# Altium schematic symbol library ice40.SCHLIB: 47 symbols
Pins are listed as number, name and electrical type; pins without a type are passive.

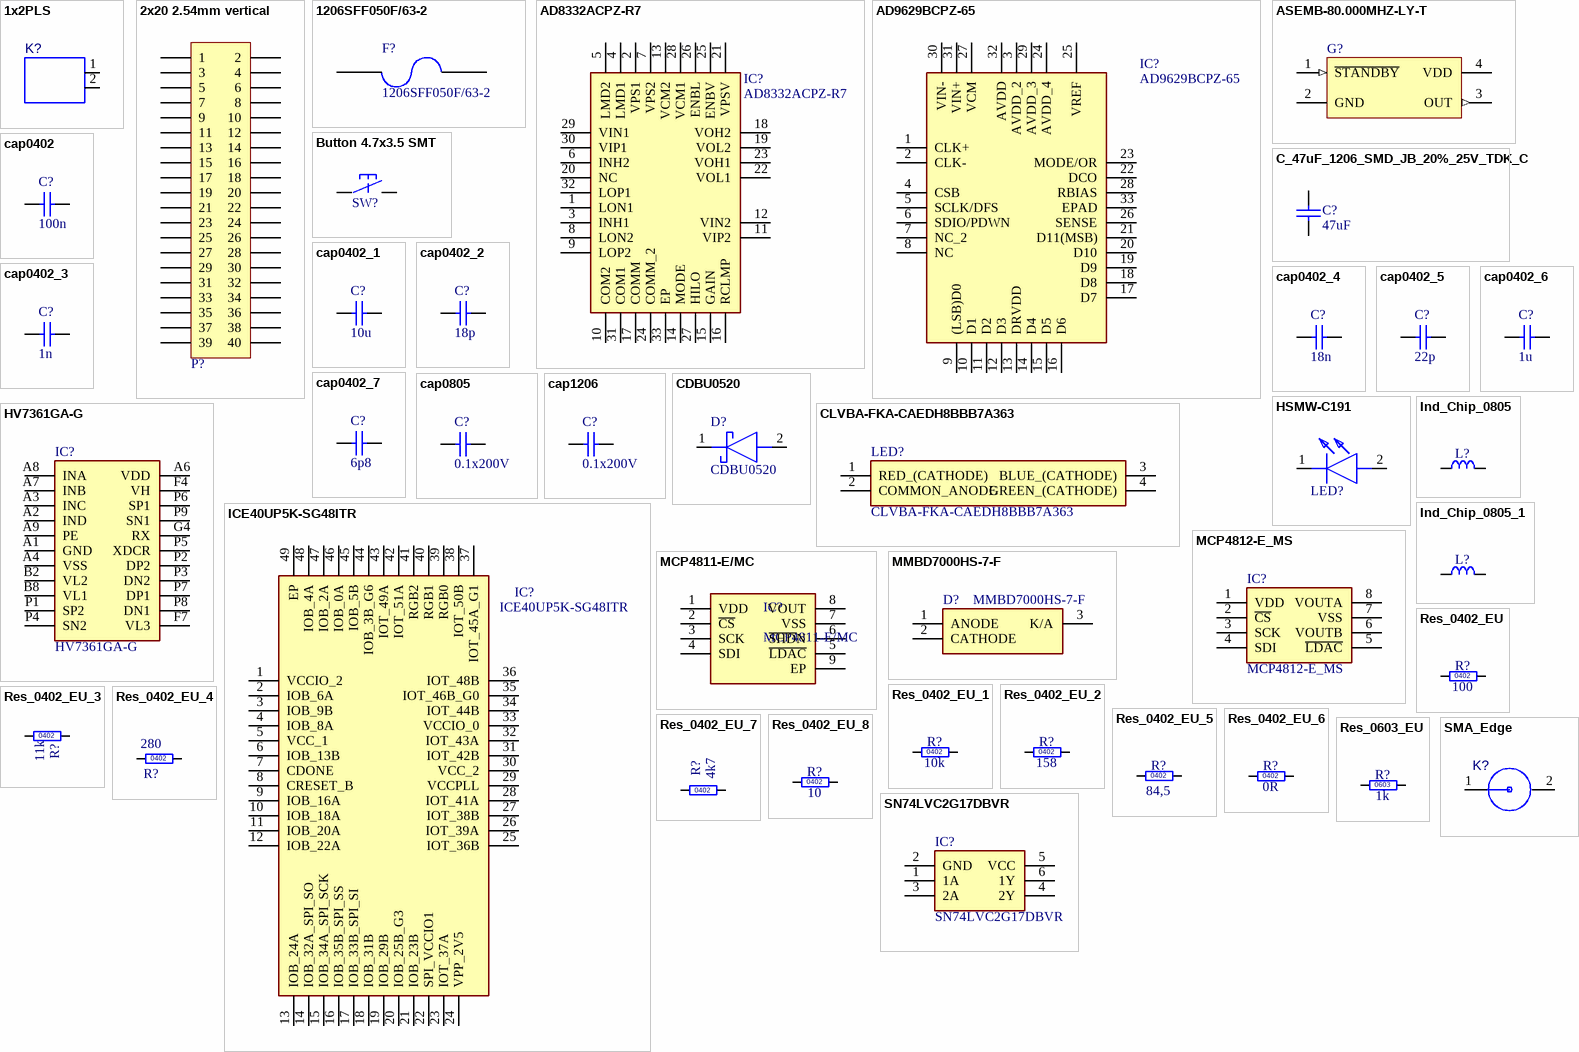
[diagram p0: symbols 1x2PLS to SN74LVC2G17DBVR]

## 1x2PLS
designator K?  (value not drawn)
footprint JUMPER2
pins: 1, 2

## 2x20 2.54mm vertical
designator P?  (value not drawn)
Header, 40-Pin
footprint PLD-40
pins: 1, 2, 3, 4, 5, 6, 7, 8, 9, 10, 11, 12, 13, 14, 15, 16, 17, 18, 19, 20, 21, 22, 23, 24, 25, 26, 27, 28, 29, 30, 31, 32, 33, 34, 35, 36, 37, 38, 39, 40

## 1206SFF050F/63-2
designator F?
500mA AC 63V DC Fuse Board Mount Surface Mount 1206; ATT Technology: SMD; ATT Fuse size: 1206
footprint FUSE_1206 (FUSE, 2-Leads, Body 3.2x1.60mm, IPC Medium Density)
pins: 1, 2

## AD8332ACPZ-R7
designator IC?
Integrated Circuit; Manufacturer_Name: Analog Devices
footprint QFN50P500X500X100-33N
pins: 1 LON1, 2 VPS1, 3 INH1, 4 LMD1, 5 LMD2, 6 INH2, 7 VPS2, 8 LON2, 9 LOP2, 10 COM2, 11 VIP2, 12 VIN2, 13 VCM2, 14 MODE, 15 GAIN, 16 RCLMP, 17 COMM, 18 VOH2, 19 VOL2, 20 NC, 21 VPSV, 22 VOL1, 23 VOH1, 24 COMM_2, 25 ENBV, 26 ENBL, 27 HILO, 28 VCM1, 29 VIN1, 30 VIP1, 31 COM1, 32 LOP1, 33 EP

## AD9629BCPZ-65
designator IC?
Integrated Circuit; Manufacturer_Name: Analog Devices
footprint QFN50P500X500X100-33N
pins: 1 CLK+, 2 CLK-, 3 AVDD_2, 4 CSB, 5 SCLK/DFS, 6 SDIO/PDWN, 7 NC_2, 8 NC, 9 (LSB)D0, 10 D1, 11 D2, 12 D3, 13 DRVDD, 14 D4, 15 D5, 16 D6, 17 D7, 18 D8, 19 D9, 20 D10, 21 D11(MSB), 22 DCO, 23 MODE/OR, 24 AVDD_4, 25 VREF, 26 SENSE, 27 VCM, 28 RBIAS, 29 AVDD_3, 30 VIN-, 31 VIN+, 32 AVDD, 33 EPAD

## ASEMB-80.000MHZ-LY-T
designator G?, comment Oscillator  (value not drawn)
OSC MEMS 80 MHZ SMD; Validation Status: Verified; ATT Frequency: 80Mhz; ATT Frequency Stability: ±10ppm; ATT Package / Case: 4-SMD, No Lead (DFN, LCC); ATT Series: ASEMB, Pure Silicon™; ATT Supply Current: 16mA; ATT Supply Voltage: 1.7 V ~ 3.6 V; ATT Type: MEMS (Silicon)
footprint OSC_ASEM
pins: 1 ~{STANDBY} (in), 2 GND (power), 3 OUT (out), 4 VDD (power)

## Button 4.7x3.5 SMT
designator SW?, comment EVQ-P9P02M  (value not drawn)
footprint Button 4.7x3.5 _SMT (EVQ-P9P02M_SMT)
pins: 1, 2, 3, 4

## C_47uF_1206_SMD_JB_20%_25V_TDK_C
designator C?, comment value 47uF  (hidden comment: Capacitor)
CAP CER 47UF 25V X5R 1206; ManufacturerPartNumber: C3216JB1E476M160AC; Validation Status: Verified; ATT Capacitor Type: Ceramic; ATT Case: 1206 (3216 Metric); ATT Temperature Coefficient: JB; ATT Tolerance: ±20%
footprint CAP_CERAMIC_1206
pins: 1, 2

## cap0402
designator C?  value 100n  (hidden comment: cap0402)
Capacitor  0402 inch
footprint SM0402_3D_cap (0402 cap)
pins: 1, 2

## cap0402_1
designator C?, comment value 10u  (hidden comment: cap0402)
Capacitor  0402 inch
footprint SM0402_3D_cap (0402 cap)
pins: 1, 2

## cap0402_2
designator C?, comment value 18p  (hidden comment: cap0402)
Capacitor  0402 inch
footprint SM0402_3D_cap (0402 cap)
pins: 1, 2

## cap0402_3
designator C?, comment value 1n  (hidden comment: cap0402)
Capacitor  0402 inch
footprint SM0402_3D_cap (0402 cap)
pins: 1, 2

## cap0402_4
designator C?, comment value 18n  (hidden comment: cap0402)
Capacitor  0402 inch
footprint SM0402_3D_cap (0402 cap)
pins: 1, 2

## cap0402_5
designator C?, comment value 22p  (hidden comment: cap0402)
Capacitor  0402 inch
footprint SM0402_3D_cap (0402 cap)
pins: 1, 2

## cap0402_6
designator C?, comment value 1u  (hidden comment: cap0402)
Capacitor  0402 inch
footprint SM0402_3D_cap (0402 cap)
pins: 1, 2

## cap0402_7
designator C?, comment value 6p8  (hidden comment: cap0402)
Capacitor  0402 inch
footprint SM0402_3D_cap (0402 cap)
pins: 1, 2

## cap0805
designator C?  value 0.1x200V  (hidden comment: cap0805)
Capacitor
signal-integrity model Cap
footprint SM0805
pins: 1, 2

## cap1206
designator C?  value 0.1x200V  (hidden comment: cap1206)
Capacitor
signal-integrity model Cap
footprint SM1206
pins: 1, 2

## CDBU0520
designator D?
Schottky Diode; Manufacturer_Name: Comchip Technology
footprint DIOC1709X85N
pins: 1 K, 2 A

## CLVBA-FKA-CAEDH8BBB7A363
designator LED?
LED; Manufacturer_Name: Cree
footprint CLVBAFKACAEDH8BBB7A363
pins: 1 RED_(CATHODE), 2 COMMON_ANODE, 3 BLUE_(CATHODE), 4 GREEN_(CATHODE)

## HSMW-C191
designator LED?  (value not drawn)
LED; Manufacturer_Name: Avago Technologies
footprint LEDC1608X70N
pins: 1 K, 2 A

## HV7361GA-G
designator IC?
Integrated Circuit; Manufacturer_Name: Microchip
footprint BGA22C50P9X14_500X700X105
pins: A1 GND, A2 IND, A3 INC, A4 VSS, A6 VDD, A7 INB, A8 INA, A9 PE, B2 VL2, B8 VL1, F4 VH, F7 VL3, G4 RX, P1 SP2, P2 DP2, P3 DN2, P4 SN2, P5 XDCR, P6 SP1, P7 DP1, P8 DN1, P9 SN1

## ICE40UP5K-SG48ITR
designator IC?
Integrated Circuit; Manufacturer_Name: Lattice Semiconductor
footprint QFN50P700X700X100-49N-D
pins: 1 VCCIO_2, 2 IOB_6A, 3 IOB_9B, 4 IOB_8A, 5 VCC_1, 6 IOB_13B, 7 CDONE, 8 CRESET_B, 9 IOB_16A, 10 IOB_18A, 11 IOB_20A, 12 IOB_22A, 13 IOB_24A, 14 IOB_32A_SPI_SO, 15 IOB_34A_SPI_SCK, 16 IOB_35B_SPI_SS, 17 IOB_33B_SPI_SI, 18 IOB_31B, 19 IOB_29B, 20 IOB_25B_G3, 21 IOB_23B, 22 SPI_VCCIO1, 23 IOT_37A, 24 VPP_2V5, 25 IOT_36B, 26 IOT_39A, 27 IOT_38B, 28 IOT_41A, 29 VCCPLL, 30 VCC_2, 31 IOT_42B, 32 IOT_43A, 33 VCCIO_0, 34 IOT_44B, 35 IOT_46B_G0, 36 IOT_48B, 37 IOT_45A_G1, 38 IOT_50B, 39 RGB0, 40 RGB1, 41 RGB2, 42 IOT_51A, 43 IOT_49A, 44 IOB_3B_G6, 45 IOB_5B, 46 IOB_0A, 47 IOB_2A, 48 IOB_4A, 49 EP

## Ind_Chip_0805
designator L?, comment 75R@100MHz  (value not drawn)
Ferrite Beads Multi-Layer 600Ohm 25% 100MHz 1A 0.2Ohm DCR 0603 T/R; Part Number: IND0805_MURATA_BLM21BB750SN1D; Part Description: SMD EMIFIL Suppression Chip Ferrite Bead; Manufacturer: MURATA; Manufacturer Part Number: BLM21BB750SN1D; ManufacturerPartNumber: PBY160808T-601Y-N; Power: 700mA; Resistance: 0.16R; Table: Inductors SMD
footprint SM_0805_INDUCTANCE _3D (chip inductanse 0805 inch)
pins: 1, 2

## Ind_Chip_0805_1
designator L?, comment 75R@100MHz  (value not drawn)
chip inductance; Part Number: IND0805_MURATA_BLM21BB750SN1D; Part Description: SMD EMIFIL Suppression Chip Ferrite Bead; Manufacturer: MURATA; Manufacturer Part Number: AIML-0805HC-1R5M-T; Power: 700mA; Resistance: 0.16R; Tolerance: ±25%; Table: Inductors SMD
footprint SM_0805_INDUCTANCE _3D (chip inductanse 0805 inch)
pins: 1, 2

## MCP4811-E/MC
designator IC?
DAC 1-CH Resistor-String 10-bit Automotive 8-Pin DFN EP Tube; Manufacturer: Microchip; Resolution: 10b; Integral Nonlinearity (INL): 3.5LSB; Output Type: Voltage; Interface: SPI,Serial,3-WIRE; Number of DAC Channels: 1; Nominal Supply Current: 330uA; Max Supply Voltage: 5.5V; Min Supply Voltage: 2.7V; Operating Supply Voltage: 5V; Settling Time: 4.5us; Number of Bits: 10; Polarity: Bipolar; Input Offset Voltage (Vos): 820uV
footprint SON50P200X300X100-9N
pins: 1 VDD, 2 ~{CS}, 3 SCK, 4 SDI, 5 ~{LDAC}, 6 ~{SHD}N, 7 VSS, 8 VOUT, 9 EP

## MCP4812-E_MS
designator IC?
Integrated Circuit; Manufacturer_Name: Microchip; Manufacturer_Part_Number: MCP4812-E/MS
footprint SOP65P490X110-8N
pins: 1 VDD, 2 ~{CS}, 3 SCK, 4 SDI, 5 ~{LDAC}, 6 VOUTB, 7 VSS, 8 VOUTA

## MMBD7000HS-7-F
designator D?
Diode; Manufacturer_Name: Diodes Inc.
footprint SOT96P240X110-3N
pins: 1 ANODE, 2 CATHODE, 3 K/A

## Res_0402_EU
designator R?, comment 100
Res_0402_EU; Part Number: R1206_4K7_1%_0.25W_100PPM; Part Description: General Purpose Thick Film Chip Resistor; Manufacturer: GENERIC; Manufacturer1 Part Number: NRC12F4701TRF; Value: 4k7; Power: 0.25W; TC: ±100ppm/°C; Tolerance: ±1%; Table: Resistors SMD
footprint SM0402_3D_res (0603 inch resistor)
pins: 1, 2

## Res_0402_EU_1
designator R?, comment 10k
Res_0402_EU; Part Number: R1206_4K7_1%_0.25W_100PPM; Part Description: General Purpose Thick Film Chip Resistor; Manufacturer: GENERIC; Manufacturer1 Part Number: NRC12F4701TRF; Value: 4k7; Power: 0.25W; TC: ±100ppm/°C; Tolerance: ±1%; Table: Resistors SMD
footprint SM0402_3D_res (0603 inch resistor)
pins: 1, 2

## Res_0402_EU_2
designator R?, comment 158
Res_0402_EU; Part Number: R1206_4K7_1%_0.25W_100PPM; Part Description: General Purpose Thick Film Chip Resistor; Manufacturer: GENERIC; Manufacturer1 Part Number: NRC12F4701TRF; Value: 4k7; Power: 0.25W; TC: ±100ppm/°C; Tolerance: ±1%; Table: Resistors SMD
footprint SM0402_3D_res (0603 inch resistor)
pins: 1, 2

## Res_0402_EU_3
designator R?, comment 11k
Res_0402_EU; Part Number: R1206_4K7_1%_0.25W_100PPM; Part Description: General Purpose Thick Film Chip Resistor; Manufacturer: GENERIC; Manufacturer1 Part Number: NRC12F4701TRF; Value: 4k7; Power: 0.25W; TC: ±100ppm/°C; Tolerance: ±1%; Table: Resistors SMD
footprint SM0402_3D_res (0603 inch resistor)
pins: 1, 2

## Res_0402_EU_4
designator R?, comment 280
Res_0402_EU; Part Number: R1206_4K7_1%_0.25W_100PPM; Part Description: General Purpose Thick Film Chip Resistor; Manufacturer: GENERIC; Manufacturer1 Part Number: NRC12F4701TRF; Value: 4k7; Power: 0.25W; TC: ±100ppm/°C; Tolerance: ±1%; Table: Resistors SMD
footprint SM0402_3D_res (0603 inch resistor)
pins: 1, 2

## Res_0402_EU_5
designator R?, comment 84,5
Res_0402_EU; Part Number: R1206_4K7_1%_0.25W_100PPM; Part Description: General Purpose Thick Film Chip Resistor; Manufacturer: GENERIC; Manufacturer1 Part Number: NRC12F4701TRF; Value: 4k7; Power: 0.25W; TC: ±100ppm/°C; Tolerance: ±1%; Table: Resistors SMD
footprint SM0402_3D_res (0603 inch resistor)
pins: 1, 2

## Res_0402_EU_6
designator R?, comment 0R
Res_0402_EU; Part Number: R1206_4K7_1%_0.25W_100PPM; Part Description: General Purpose Thick Film Chip Resistor; Manufacturer: GENERIC; Manufacturer1 Part Number: NRC12F4701TRF; Value: 4k7; Power: 0.25W; TC: ±100ppm/°C; Tolerance: ±1%; Table: Resistors SMD
footprint SM0402_3D_res (0603 inch resistor)
pins: 1, 2

## Res_0402_EU_7
designator R?, comment 4k7
Res_0402_EU; Part Number: R1206_4K7_1%_0.25W_100PPM; Part Description: General Purpose Thick Film Chip Resistor; Manufacturer: GENERIC; Manufacturer1 Part Number: NRC12F4701TRF; Power: 0.25W; TC: ±100ppm/°C; Tolerance: ±1%; Table: Resistors SMD
footprint SM0402_3D_res (0603 inch resistor)
pins: 1, 2

## Res_0402_EU_8
designator R?, comment 10
Res_0402_EU; Part Number: R1206_4K7_1%_0.25W_100PPM; Part Description: General Purpose Thick Film Chip Resistor; Manufacturer: GENERIC; Manufacturer1 Part Number: NRC12F4701TRF; Value: 4k7; Power: 0.25W; TC: ±100ppm/°C; Tolerance: ±1%; Table: Resistors SMD
footprint SM0402_3D_res (0603 inch resistor)
pins: 1, 2

## Res_0603_EU
designator R?, comment 1k
Res_0603_EU; Part Number: R1206_4K7_1%_0.25W_100PPM; Part Description: General Purpose Thick Film Chip Resistor; Manufacturer: GENERIC; Manufacturer1 Part Number: NRC12F4701TRF; Value: 4k7; Power: 0.25W; TC: ±100ppm/°C; Tolerance: ±1%; Table: Resistors SMD
footprint SM0603_3D_res (0603 inch resistor)
pins: 1, 2

## SMA_Edge
designator K?  (value not drawn)
footprint AMPHENOL_132357-11
pins: 1, 2

## SN74LVC2G17DBVR
designator IC?
Integrated Circuit; Manufacturer_Name: Texas Instruments
footprint SOT95P280X145-6N
pins: 1 1A, 2 GND, 3 2A, 4 2Y, 5 VCC, 6 1Y

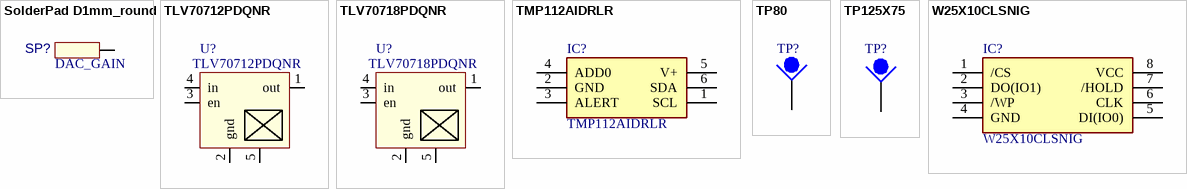
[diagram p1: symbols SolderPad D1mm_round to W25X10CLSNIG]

## SolderPad D1mm_round
designator SP?  value DAC_GAIN  (hidden comment: SolderPad D1mm_round)  (no BOM)
for finger touch
footprint SolderPad_D1mm _round (7mm solder circle for finger touch)
pins: 1

## TLV70712PDQNR
designator U?
low drop LDO
footprint X2SON - 2 (DQN, X2SON)
pins: 1 out, 2 gnd, 3 en, 4 in, 5 tp

## TLV70718PDQNR
designator U?
low drop LDO
footprint X2SON - 2 (DQN, X2SON)
pins: 1 out, 2 gnd, 3 en, 4 in, 5 tp

## TMP112AIDRLR
designator IC?
Integrated Circuit; Manufacturer_Name: Texas Instruments
footprint SOTFL50P160X60-6N
pins: 1 SCL, 2 GND, 3 ALERT, 4 ADD0, 5 V+, 6 SDA

## TP80
designator TP?  (value not drawn)  (no BOM)
footprint TP80_no_silk
footprint TP80_no_silk
pins: 1

## TP125X75
designator TP?  (value not drawn)  (no BOM)
footprint TP125X75
pins: 1

## W25X10CLSNIG
designator IC?
Integrated Circuit; Manufacturer_Name: Winbond
footprint SOIC127P600X175-8N
pins: 1 /CS, 2 DO(IO1), 3 /WP, 4 GND, 5 DI(IO0), 6 CLK, 7 /HOLD, 8 VCC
